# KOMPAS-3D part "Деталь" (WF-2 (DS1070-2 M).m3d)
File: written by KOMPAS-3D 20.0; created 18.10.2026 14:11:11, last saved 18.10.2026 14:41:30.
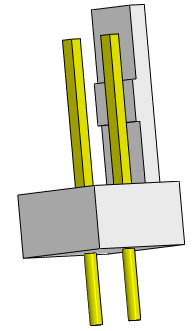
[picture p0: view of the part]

Document properties: Полное имя файла: D:\myProjects\Progect_esp32\box_compas\разъемы\WF-2 (DS1070-2 M).m3d

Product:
- Part/product: Деталь
    Масса: 0.000929543
  - Body: Тело 1
      Масса: 0.000920864

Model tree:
1. Эскиз:1
2. Элемент выдавливания:1
     Расстояние 1 = 5.08
3. Эскиз:2  (with: Элемент выдавливания:1)
4. Элемент выдавливания:2
     Расстояние 2 = 1.27
5. Эскиз:3  (with: Элемент выдавливания:1)
6. Элемент выдавливания:3
     Расстояние 2 = 1.27
7. Эскиз:4  (with: Элемент выдавливания:1)
8. Элемент выдавливания:4
     Расстояние 1 = 3.4
9. Массив по сетке:1  (with: Элемент выдавливания:4, Эскиз:4)  (2 pattern instances)
     Шаг 1 = 2.54; Угол раствора = 90
10. Эскиз:5  (with: Элемент выдавливания:1, Элемент выдавливания:4, Элемент выдавливания:2, Элемент выдавливания:3)
11. Элемент выдавливания:5
     Расстояние 1 = 7.15
12. Массив по сетке:3  (with: Элемент выдавливания:5, Эскиз:5, Элемент выдавливания:1)  (2 pattern instances)
     Шаг 1 = 2.54; Угол раствора = 90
